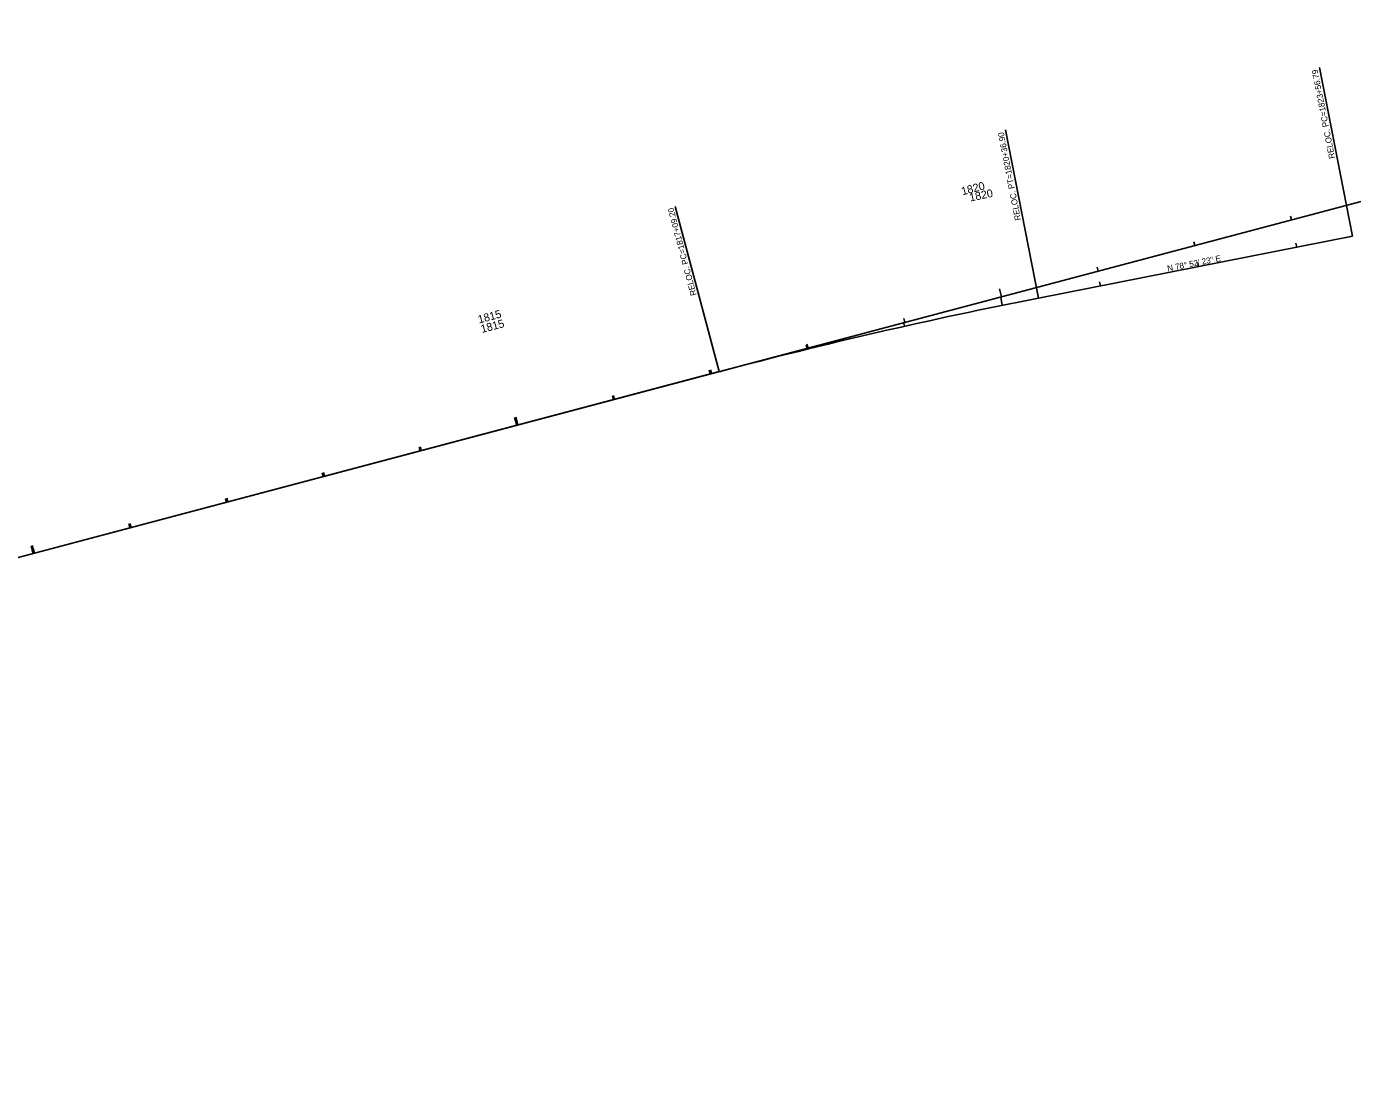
# Model space of a CAD drawing. Extents: x 2106154 to 2121963, y 864504 to 868517.
# Drawn here: x 2112084 to 2113410, y 867153 to 868210 of the extents above; entities that cross this region are included whole.
import ezdxf

# ---------------------------------------------------------------- set-up
doc = ezdxf.new("R2010")
doc.units = 0
for name, color, linetype in [('RD_HC_Data_Tic_Rel', 7, 'Continuous'), ('RD_HC_TX_Rel_Sta50', 7, 'Continuous'), ('RD_PD_EarthShd', 7, 'Continuous'), ('RD_PD_EOP', 7, 'Continuous'), ('RD_PD_Final_LnLine', 7, 'Continuous'), ('RD_Sketch1', 7, 'Continuous'), ('RD_Sketch10', 7, 'Continuous')]:
    doc.layers.add(name, color=color, linetype=linetype)

msp = doc.modelspace()

# ---------------------------------------------------------------- linework, layer by layer
at = {"layer": 'RD_HC_Data_Tic_Rel'}
for p, q in [((2113095.6, 867938.7), (2113409.5, 868000.5)), ((2111352, 867487.6), (2112776.4, 867865.1))]:
    msp.add_line(p, q, dxfattribs=at)
msp.add_arc((2114070.2, 862983.6), 5050, 101.1268, 104.8448, dxfattribs=at)
at = {"layer": 'RD_HC_TX_Rel_Sta50'}
for p, q in [((2113409.5, 868000.5), (2113376.4, 868169)), ((2113095.6, 867938.7), (2113062.6, 868106.6)), ((2112776.4, 867865.1), (2112732.6, 868030.1))]:
    msp.add_line(p, q, dxfattribs=at)
at = {"layer": 'RD_PD_EarthShd'}
for p, q in [((2113348.7, 868016.8), (2113347.7, 868020.6)), ((2113252, 867991.2), (2113251, 867995)), ((2113155.4, 867965.5), (2113154.3, 867969.4)), ((2113058.7, 867939.9), (2113056.6, 867947.7)), ((2112962, 867914.3), (2112961, 867918.2)), ((2112865.4, 867888.7), (2112864.3, 867892.5)), ((2112768.7, 867863.1), (2112767.7, 867866.9)), ((2112672, 867837.4), (2112671, 867841.3)), ((2112575.4, 867811.8), (2112573.3, 867819.6)), ((2112478.7, 867786.2), (2112477.7, 867790.1)), ((2112382.1, 867760.6), (2112381, 867764.4)), ((2112285.4, 867735), (2112284.4, 867738.8)), ((2112188.7, 867709.3), (2112187.7, 867713.2)), ((2112092.1, 867683.7), (2112090, 867691.5))]:
    msp.add_line(p, q, dxfattribs=at)
at = {"layer": 'RD_PD_EOP'}
msp.add_line((2110088.7, 867152.7), (2114077.7, 868210), dxfattribs=at)
at = {"layer": 'RD_Sketch1'}
for p, q in [((2113353.8, 867989.5), (2113353, 867993.4)), ((2113255.7, 867970.2), (2113254.9, 867974.1)), ((2113157.6, 867950.9), (2113156.8, 867954.8)), ((2113059.5, 867931.5), (2113057.9, 867939.3)), ((2112961.7, 867910.5), (2112960.8, 867914.4)), ((2112864.4, 867887.6), (2112863.4, 867891.5)), ((2112767.5, 867862.7), (2112766.5, 867866.6)), ((2112670.8, 867837.1), (2112669.8, 867841)), ((2112574.2, 867811.5), (2112572.1, 867819.2)), ((2112477.5, 867785.9), (2112476.5, 867789.7)), ((2112380.8, 867760.3), (2112379.8, 867764.1)), ((2112284.2, 867734.6), (2112283.2, 867738.5)), ((2112187.5, 867709), (2112186.5, 867712.9)), ((2112090.9, 867683.4), (2112088.8, 867691.1))]:
    msp.add_line(p, q, dxfattribs=at)

# ---------------------------------------------------------------- texts
at = {"layer": 'RD_HC_TX_Rel_Sta50'}
for s, rotation, p in [('RELOC. PC=1823+56.79', 101.1268, (2113392.1, 868078.6)), ('RELOC. PT=1820+36.90', 101.1268, (2113078.2, 868016.8)), ('RELOC. PC=1817+09.20', 104.8448, (2112754, 867941.9)), ('N 78%%d 52\' 23" E', 11.1268, (2113225, 867965.2))]:
    msp.add_text(s, height=6, rotation=rotation, dxfattribs=at).set_placement(p)
at = {"layer": 'RD_PD_Final_LnLine'}
for s, p in [('1820', (2113019.7, 868041.3)), ('1815', (2112536.5, 867913.2))]:
    msp.add_text(s, height=8, rotation=14.8448, dxfattribs=at).set_placement(p)
at = {"layer": 'RD_Sketch10'}
for s, rotation, p in [('1820', 11.5455, (2113027.4, 868035.1)), ('1815', 14.8448, (2112539.4, 867903.7))]:
    msp.add_text(s, height=8, rotation=rotation, dxfattribs=at).set_placement(p)

doc.saveas('drawing.dxf')
